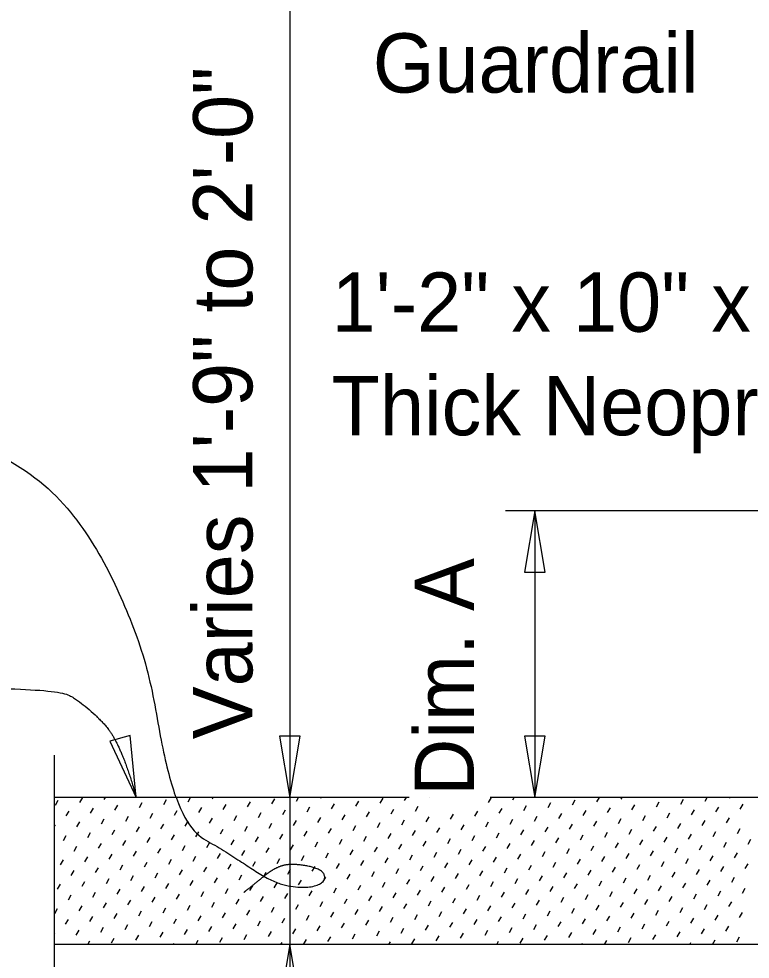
# Model space of a CAD drawing. Extents: x 21516.9 to 21589, y 56153.3 to 56193.5.
# Drawn here: x 21520.841 to 21523.329, y 56182.575 to 56185.773 of the extents above; entities that cross this region are included whole.
import ezdxf

# ---------------------------------------------------------------- set-up
doc = ezdxf.new("R2010")
doc.units = 0
for name, color, linetype in [('AdhocPoint_dp', 7, 'Continuous'), ('PlotBorder_dp', 7, 'Continuous'), ('SheetBorder_dp', 7, 'Continuous'), ('TextMisc', 7, 'Continuous')]:
    doc.layers.add(name, color=color, linetype=linetype)

msp = doc.modelspace()

# ---------------------------------------------------------------- linework, layer by layer
at = {"layer": 'AdhocPoint_dp'}
msp.add_line((21524.8963, 56182.6248), (21520.9629, 56182.6248), dxfattribs=at)
at = {"layer": 'PlotBorder_dp'}
for p, q in [((21521.7632, 56188.4582), (21521.7632, 56181.4582)), ((21524.9938, 56184.0995), (21522.4966, 56184.0995)), ((21522.5966, 56184.0995), (21522.5966, 56183.1248))]:
    msp.add_line(p, q, dxfattribs=at)
for points in [[(21522.5966, 56184.0995), (21522.5614, 56183.8912), (21522.6319, 56183.8912)], [(21521.2406, 56183.1248), (21521.2194, 56183.335), (21521.1513, 56183.3162)], [(21521.7632, 56183.1248), (21521.7985, 56183.3331), (21521.7279, 56183.3331)], [(21522.5966, 56183.1248), (21522.6319, 56183.3331), (21522.5614, 56183.3331)], [(21521.7632, 56182.6248), (21521.7279, 56182.4166), (21521.7985, 56182.4166)]]:
    msp.add_lwpolyline(points, close=True, dxfattribs=at)
msp.add_lwpolyline([(21520.963, 56181.2978), (21520.963, 56182.1975), (21520.8597, 56182.1975), (21520.963, 56182.2425), (21521.0664, 56182.2875), (21520.963, 56182.2875), (21520.963, 56183.2682)], dxfattribs=at)
for points in [[(21519.9826, 56184.4791), (21520.8234, 56184.3928), (21521.2569, 56183.7454), (21521.3674, 56183.0454), (21521.5657, 56182.9278), (21521.7074, 56182.8329), (21521.8124, 56182.8145), (21521.8818, 56182.833), (21521.8818, 56182.8741), (21521.8109, 56182.8968), (21521.7245, 56182.8968), (21521.6338, 56182.823), (21521.6069, 56182.8017)], [(21520.2586, 56183.4916), (21520.9544, 56183.5086), (21521.0791, 56183.432), (21521.1896, 56183.31), (21521.2406, 56183.1248)]]:
    msp.add_open_spline(points, degree=2, dxfattribs=at)
at = {"layer": 'TextMisc'}
for p, q in [((21522.1691, 56183.1248), (21520.9629, 56183.1248)), ((21520.9657, 56183.0984), (21520.9755, 56183.1152)), ((21521.0487, 56183.1081), (21521.0584, 56183.1248)), ((21521.1316, 56183.1178), (21521.1357, 56183.1248)), ((21521.3341, 56183.1007), (21521.3438, 56183.1175)), ((21521.417, 56183.1104), (21521.4254, 56183.1248)), ((21521.5, 56183.1201), (21521.5027, 56183.1248)), ((21521.6195, 56183.0932), (21521.6292, 56183.11)), ((21521.7024, 56183.1029), (21521.7122, 56183.1197)), ((21521.7854, 56183.1127), (21521.7924, 56183.1248)), ((21521.8683, 56183.1224), (21521.8697, 56183.1248)), ((21521.9879, 56183.0955), (21521.9976, 56183.1123)), ((21522.0708, 56183.1052), (21522.0805, 56183.122)), ((21522.1537, 56183.1149), (21522.1595, 56183.1248)), ((21522.2367, 56183.1247), (21522.2368, 56183.1248)), ((21522.4392, 56183.1075), (21522.4489, 56183.1243)), ((21524.955, 56183.1248), (21522.4449, 56183.1248)), ((21522.5221, 56183.1172), (21522.5265, 56183.1248)), ((21522.7246, 56183.1001), (21522.7343, 56183.1169)), ((21522.8075, 56183.1098), (21522.8162, 56183.1248)), ((21522.8905, 56183.1195), (21522.8935, 56183.1248)), ((21523.0929, 56183.1024), (21523.1027, 56183.1191)), ((21523.1759, 56183.1121), (21523.1833, 56183.1248)), ((21523.2588, 56183.1218), (21523.2606, 56183.1248)), ((21521.0023, 56183.0618), (21521.0121, 56183.0786)), ((21521.0853, 56183.0715), (21521.095, 56183.0883)), ((21521.1682, 56183.0812), (21521.1779, 56183.098)), ((21521.2512, 56183.0909), (21521.2609, 56183.1077)), ((21521.3707, 56183.0641), (21521.3804, 56183.0808)), ((21521.4536, 56183.0738), (21521.4634, 56183.0906)), ((21521.5366, 56183.0835), (21521.5463, 56183.1003)), ((21521.7391, 56183.0663), (21521.7488, 56183.0831)), ((21521.822, 56183.0761), (21521.8317, 56183.0929)), ((21521.9049, 56183.0858), (21521.9147, 56183.1026)), ((21522.1074, 56183.0686), (21522.1171, 56183.0854)), ((21522.1904, 56183.0783), (21522.2001, 56183.0951)), ((21522.3928, 56183.0612), (21522.4026, 56183.078)), ((21522.4758, 56183.0709), (21522.4855, 56183.0877)), ((21522.5587, 56183.0806), (21522.5684, 56183.0974)), ((21522.6416, 56183.0903), (21522.6514, 56183.1071)), ((21522.7612, 56183.0635), (21522.7709, 56183.0803)), ((21522.8441, 56183.0732), (21522.8539, 56183.09)), ((21522.9271, 56183.0829), (21522.9368, 56183.0997)), ((21523.01, 56183.0926), (21523.0197, 56183.1094)), ((21523.1296, 56183.0657), (21523.1393, 56183.0825)), ((21523.2125, 56183.0755), (21523.2222, 56183.0923)), ((21523.2954, 56183.0852), (21523.3052, 56183.102)), ((21521.1219, 56183.0349), (21521.1316, 56183.0517)), ((21521.2048, 56183.0446), (21521.2145, 56183.0614)), ((21521.2878, 56183.0543), (21521.2975, 56183.0711)), ((21521.4902, 56183.0372), (21521.5, 56183.054)), ((21521.5732, 56183.0469), (21521.5829, 56183.0637)), ((21521.6561, 56183.0566), (21521.6658, 56183.0734)), ((21521.7757, 56183.0297), (21521.7854, 56183.0465)), ((21521.8586, 56183.0395), (21521.8683, 56183.0562)), ((21521.9415, 56183.0492), (21521.9513, 56183.066)), ((21522.0245, 56183.0589), (21522.0342, 56183.0757)), ((21522.144, 56183.032), (21522.1537, 56183.0488)), ((21522.227, 56183.0417), (21522.2367, 56183.0585)), ((21522.3099, 56183.0515), (21522.3196, 56183.0683)), ((21522.5124, 56183.0343), (21522.5221, 56183.0511)), ((21522.5953, 56183.044), (21522.605, 56183.0608)), ((21522.6783, 56183.0537), (21522.688, 56183.0705)), ((21522.8807, 56183.0366), (21522.8905, 56183.0534)), ((21522.9637, 56183.0463), (21522.9734, 56183.0631)), ((21523.0466, 56183.056), (21523.0563, 56183.0728)), ((21523.1662, 56183.0291), (21523.1759, 56183.0459)), ((21523.2491, 56183.0389), (21523.2588, 56183.0557)), ((21520.9629, 56183.0274), (21520.9657, 56183.0322)), ((21521.0389, 56183.0252), (21521.0487, 56183.042)), ((21521.1585, 56182.9983), (21521.1682, 56183.0151)), ((21521.2414, 56183.008), (21521.2512, 56183.0248)), ((21521.3244, 56183.0177), (21521.3341, 56183.0345)), ((21521.4073, 56183.0274), (21521.417, 56183.0442)), ((21521.5269, 56183.0006), (21521.5366, 56183.0174)), ((21521.6098, 56183.0103), (21521.6195, 56183.0271)), ((21521.6927, 56183.02), (21521.7024, 56183.0368)), ((21521.8952, 56183.0028), (21521.9049, 56183.0196)), ((21521.9781, 56183.0126), (21521.9879, 56183.0294)), ((21522.0611, 56183.0223), (21522.0708, 56183.0391)), ((21522.2636, 56183.0051), (21522.2733, 56183.0219)), ((21522.3465, 56183.0148), (21522.3562, 56183.0316)), ((21522.4294, 56183.0246), (21522.4392, 56183.0414)), ((21522.549, 56182.9977), (21522.5587, 56183.0145)), ((21522.6319, 56183.0074), (21522.6416, 56183.0242)), ((21522.7149, 56183.0171), (21522.7246, 56183.0339)), ((21522.7978, 56183.0269), (21522.8075, 56183.0436)), ((21522.9173, 56183), (21522.9271, 56183.0168)), ((21523.0003, 56183.0097), (21523.01, 56183.0265)), ((21523.0832, 56183.0194), (21523.0929, 56183.0362)), ((21523.2857, 56183.0023), (21523.2954, 56183.019)), ((21520.9926, 56182.9788), (21521.0023, 56182.9956)), ((21521.0756, 56182.9886), (21521.0853, 56183.0053)), ((21521.278, 56182.9714), (21521.2878, 56182.9882)), ((21521.361, 56182.9811), (21521.3707, 56182.9979)), ((21521.4439, 56182.9908), (21521.4536, 56183.0076)), ((21521.6464, 56182.9737), (21521.6561, 56182.9905)), ((21521.7293, 56182.9834), (21521.7391, 56183.0002)), ((21521.8123, 56182.9931), (21521.822, 56183.0099)), ((21521.9318, 56182.9662), (21521.9415, 56182.983)), ((21522.0148, 56182.976), (21522.0245, 56182.9928)), ((21522.0977, 56182.9857), (21522.1074, 56183.0025)), ((21522.1806, 56182.9954), (21522.1904, 56183.0122)), ((21522.3002, 56182.9685), (21522.3099, 56182.9853)), ((21522.3831, 56182.9782), (21522.3928, 56182.995)), ((21522.4661, 56182.988), (21522.4758, 56183.0048)), ((21522.6685, 56182.9708), (21522.6783, 56182.9876)), ((21522.7515, 56182.9805), (21522.7612, 56182.9973)), ((21522.8344, 56182.9902), (21522.8441, 56183.007)), ((21523.0369, 56182.9731), (21523.0466, 56182.9899)), ((21523.1198, 56182.9828), (21523.1296, 56182.9996)), ((21523.2028, 56182.9925), (21523.2125, 56183.0093)), ((21523.3223, 56182.9656), (21523.332, 56182.9824)), ((21521.0292, 56182.9422), (21521.0389, 56182.959)), ((21521.1122, 56182.9519), (21521.1219, 56182.9687)), ((21521.1951, 56182.9617), (21521.2048, 56182.9785)), ((21521.3146, 56182.9348), (21521.3244, 56182.9516)), ((21521.3976, 56182.9445), (21521.4073, 56182.9613)), ((21521.4805, 56182.9542), (21521.4902, 56182.971)), ((21521.5635, 56182.964), (21521.5732, 56182.9807)), ((21521.683, 56182.9371), (21521.6927, 56182.9539)), ((21521.7659, 56182.9468), (21521.7757, 56182.9636)), ((21521.8489, 56182.9565), (21521.8586, 56182.9733)), ((21522.0514, 56182.9394), (21522.0611, 56182.9561)), ((21522.1343, 56182.9491), (21522.144, 56182.9659)), ((21522.2172, 56182.9588), (21522.227, 56182.9756)), ((21522.4197, 56182.9416), (21522.4294, 56182.9584)), ((21522.5027, 56182.9514), (21522.5124, 56182.9682)), ((21522.5856, 56182.9611), (21522.5953, 56182.9779)), ((21522.7051, 56182.9342), (21522.7149, 56182.951)), ((21522.7881, 56182.9439), (21522.7978, 56182.9607)), ((21522.871, 56182.9536), (21522.8807, 56182.9704)), ((21522.954, 56182.9634), (21522.9637, 56182.9802)), ((21523.0735, 56182.9365), (21523.0832, 56182.9533)), ((21523.1564, 56182.9462), (21523.1662, 56182.963)), ((21523.2394, 56182.9559), (21523.2491, 56182.9727)), ((21521.0658, 56182.9056), (21521.0756, 56182.9224)), ((21521.1488, 56182.9153), (21521.1585, 56182.9321)), ((21521.2317, 56182.9251), (21521.2414, 56182.9419)), ((21521.4342, 56182.9079), (21521.4439, 56182.9247)), ((21521.5171, 56182.9176), (21521.5269, 56182.9344)), ((21521.6001, 56182.9273), (21521.6098, 56182.9441)), ((21521.8025, 56182.9102), (21521.8123, 56182.927)), ((21521.8855, 56182.9199), (21521.8952, 56182.9367)), ((21521.9684, 56182.9296), (21521.9781, 56182.9464)), ((21522.088, 56182.9027), (21522.0977, 56182.9195)), ((21522.1709, 56182.9125), (21522.1806, 56182.9293)), ((21522.2538, 56182.9222), (21522.2636, 56182.939)), ((21522.3368, 56182.9319), (21522.3465, 56182.9487)), ((21522.4563, 56182.905), (21522.4661, 56182.9218)), ((21522.5393, 56182.9147), (21522.549, 56182.9315)), ((21522.6222, 56182.9245), (21522.6319, 56182.9413)), ((21522.8247, 56182.9073), (21522.8344, 56182.9241)), ((21522.9076, 56182.917), (21522.9173, 56182.9338)), ((21522.9906, 56182.9268), (21523.0003, 56182.9435)), ((21523.193, 56182.9096), (21523.2028, 56182.9264)), ((21523.276, 56182.9193), (21523.2857, 56182.9361)), ((21520.9829, 56182.8959), (21520.9926, 56182.9127)), ((21521.1024, 56182.869), (21521.1122, 56182.8858)), ((21521.1854, 56182.8787), (21521.1951, 56182.8955)), ((21521.2683, 56182.8885), (21521.278, 56182.9052)), ((21521.3513, 56182.8982), (21521.361, 56182.915)), ((21521.4708, 56182.8713), (21521.4805, 56182.8881)), ((21521.5537, 56182.881), (21521.5635, 56182.8978)), ((21521.6367, 56182.8907), (21521.6464, 56182.9075)), ((21521.7196, 56182.9005), (21521.7293, 56182.9173)), ((21521.8392, 56182.8736), (21521.8489, 56182.8904)), ((21521.9221, 56182.8833), (21521.9318, 56182.9001)), ((21522.005, 56182.893), (21522.0148, 56182.9098)), ((21522.2075, 56182.8759), (21522.2172, 56182.8927)), ((21522.2905, 56182.8856), (21522.3002, 56182.9024)), ((21522.3734, 56182.8953), (21522.3831, 56182.9121)), ((21522.5759, 56182.8781), (21522.5856, 56182.8949)), ((21522.6588, 56182.8879), (21522.6685, 56182.9047)), ((21522.7417, 56182.8976), (21522.7515, 56182.9144)), ((21522.8613, 56182.8707), (21522.871, 56182.8875)), ((21522.9442, 56182.8804), (21522.954, 56182.8972)), ((21523.0272, 56182.8901), (21523.0369, 56182.9069)), ((21523.1101, 56182.8999), (21523.1198, 56182.9167)), ((21523.2297, 56182.873), (21523.2394, 56182.8898)), ((21523.3126, 56182.8827), (21523.3223, 56182.8995)), ((21521.0195, 56182.8593), (21521.0292, 56182.8761)), ((21521.222, 56182.8421), (21521.2317, 56182.8589)), ((21521.3049, 56182.8518), (21521.3146, 56182.8686)), ((21521.3879, 56182.8616), (21521.3976, 56182.8784)), ((21521.5903, 56182.8444), (21521.6001, 56182.8612)), ((21521.6733, 56182.8541), (21521.683, 56182.8709)), ((21521.7562, 56182.8639), (21521.7659, 56182.8806)), ((21521.8758, 56182.837), (21521.8855, 56182.8538)), ((21521.9587, 56182.8467), (21521.9684, 56182.8635)), ((21522.0416, 56182.8564), (21522.0514, 56182.8732)), ((21522.1246, 56182.8661), (21522.1343, 56182.8829)), ((21522.2441, 56182.8393), (21522.2538, 56182.856)), ((21522.3271, 56182.849), (21522.3368, 56182.8658)), ((21522.41, 56182.8587), (21522.4197, 56182.8755)), ((21522.4929, 56182.8684), (21522.5027, 56182.8852)), ((21522.6125, 56182.8415), (21522.6222, 56182.8583)), ((21522.6954, 56182.8513), (21522.7051, 56182.8681)), ((21522.7784, 56182.861), (21522.7881, 56182.8778)), ((21522.9808, 56182.8438), (21522.9906, 56182.8606)), ((21523.0638, 56182.8535), (21523.0735, 56182.8703)), ((21523.1467, 56182.8633), (21523.1564, 56182.8801)), ((21520.9732, 56182.813), (21520.9829, 56182.8297)), ((21521.0561, 56182.8227), (21521.0658, 56182.8395)), ((21521.139, 56182.8324), (21521.1488, 56182.8492)), ((21521.2586, 56182.8055), (21521.2683, 56182.8223)), ((21521.3415, 56182.8152), (21521.3513, 56182.832)), ((21521.4245, 56182.825), (21521.4342, 56182.8418)), ((21521.5074, 56182.8347), (21521.5171, 56182.8515)), ((21521.627, 56182.8078), (21521.6367, 56182.8246)), ((21521.7099, 56182.8175), (21521.7196, 56182.8343)), ((21521.7928, 56182.8272), (21521.8025, 56182.844)), ((21521.9953, 56182.8101), (21522.005, 56182.8269)), ((21522.0782, 56182.8198), (21522.088, 56182.8366)), ((21522.1612, 56182.8295), (21522.1709, 56182.8463)), ((21522.3637, 56182.8124), (21522.3734, 56182.8292)), ((21522.4466, 56182.8221), (21522.4563, 56182.8389)), ((21522.5295, 56182.8318), (21522.5393, 56182.8486)), ((21522.6491, 56182.8049), (21522.6588, 56182.8217)), ((21522.732, 56182.8146), (21522.7417, 56182.8314)), ((21522.815, 56182.8244), (21522.8247, 56182.8412)), ((21522.8979, 56182.8341), (21522.9076, 56182.8509)), ((21523.0174, 56182.8072), (21523.0272, 56182.824)), ((21523.1004, 56182.8169), (21523.1101, 56182.8337)), ((21523.1833, 56182.8267), (21523.193, 56182.8434)), ((21523.2663, 56182.8364), (21523.276, 56182.8532)), ((21521.0098, 56182.7763), (21521.0195, 56182.7931)), ((21521.0927, 56182.7861), (21521.1024, 56182.8029)), ((21521.1757, 56182.7958), (21521.1854, 56182.8126)), ((21521.3781, 56182.7786), (21521.3879, 56182.7954)), ((21521.4611, 56182.7884), (21521.4708, 56182.8051)), ((21521.544, 56182.7981), (21521.5537, 56182.8149)), ((21521.7465, 56182.7809), (21521.7562, 56182.7977)), ((21521.8294, 56182.7906), (21521.8392, 56182.8074)), ((21521.9124, 56182.8004), (21521.9221, 56182.8172)), ((21522.0319, 56182.7735), (21522.0416, 56182.7903)), ((21522.1149, 56182.7832), (21522.1246, 56182.8)), ((21522.1978, 56182.7929), (21522.2075, 56182.8097)), ((21522.2807, 56182.8026), (21522.2905, 56182.8194)), ((21522.4003, 56182.7758), (21522.41, 56182.7926)), ((21522.4832, 56182.7855), (21522.4929, 56182.8023)), ((21522.5662, 56182.7952), (21522.5759, 56182.812)), ((21522.7686, 56182.778), (21522.7784, 56182.7948)), ((21522.8516, 56182.7878), (21522.8613, 56182.8046)), ((21522.9345, 56182.7975), (21522.9442, 56182.8143)), ((21523.137, 56182.7803), (21523.1467, 56182.7971)), ((21523.2199, 56182.79), (21523.2297, 56182.8068)), ((21523.3029, 56182.7998), (21523.3126, 56182.8166)), ((21521.1293, 56182.7495), (21521.139, 56182.7663)), ((21521.2123, 56182.7592), (21521.222, 56182.776)), ((21521.2952, 56182.7689), (21521.3049, 56182.7857)), ((21521.4147, 56182.742), (21521.4245, 56182.7588)), ((21521.4977, 56182.7517), (21521.5074, 56182.7685)), ((21521.5806, 56182.7615), (21521.5903, 56182.7783)), ((21521.6636, 56182.7712), (21521.6733, 56182.788)), ((21521.7831, 56182.7443), (21521.7928, 56182.7611)), ((21521.866, 56182.754), (21521.8758, 56182.7708)), ((21521.949, 56182.7638), (21521.9587, 56182.7805)), ((21522.1515, 56182.7466), (21522.1612, 56182.7634)), ((21522.2344, 56182.7563), (21522.2441, 56182.7731)), ((21522.3173, 56182.766), (21522.3271, 56182.7828)), ((21522.5198, 56182.7489), (21522.5295, 56182.7657)), ((21522.6028, 56182.7586), (21522.6125, 56182.7754)), ((21522.6857, 56182.7683), (21522.6954, 56182.7851)), ((21522.8052, 56182.7414), (21522.815, 56182.7582)), ((21522.8882, 56182.7512), (21522.8979, 56182.768)), ((21522.9711, 56182.7609), (21522.9808, 56182.7777)), ((21523.0541, 56182.7706), (21523.0638, 56182.7874)), ((21523.1736, 56182.7437), (21523.1833, 56182.7605)), ((21523.2565, 56182.7534), (21523.2663, 56182.7702)), ((21520.9634, 56182.73), (21520.9732, 56182.7468)), ((21521.0464, 56182.7397), (21521.0561, 56182.7565)), ((21521.1659, 56182.7129), (21521.1757, 56182.7296)), ((21521.2489, 56182.7226), (21521.2586, 56182.7394)), ((21521.3318, 56182.7323), (21521.3415, 56182.7491)), ((21521.5343, 56182.7151), (21521.544, 56182.7319)), ((21521.6172, 56182.7249), (21521.627, 56182.7417)), ((21521.7002, 56182.7346), (21521.7099, 56182.7514)), ((21521.9026, 56182.7174), (21521.9124, 56182.7342)), ((21521.9856, 56182.7271), (21521.9953, 56182.7439)), ((21522.0685, 56182.7369), (21522.0782, 56182.7537)), ((21522.1881, 56182.71), (21522.1978, 56182.7268)), ((21522.271, 56182.7197), (21522.2807, 56182.7365)), ((21522.3539, 56182.7294), (21522.3637, 56182.7462)), ((21522.4369, 56182.7392), (21522.4466, 56182.7559)), ((21522.5564, 56182.7123), (21522.5662, 56182.7291)), ((21522.6394, 56182.722), (21522.6491, 56182.7388)), ((21522.7223, 56182.7317), (21522.732, 56182.7485)), ((21522.9248, 56182.7145), (21522.9345, 56182.7313)), ((21523.0077, 56182.7243), (21523.0174, 56182.7411)), ((21523.0907, 56182.734), (21523.1004, 56182.7508)), ((21523.2931, 56182.7168), (21523.3029, 56182.7336)), ((21521.0001, 56182.6934), (21521.0098, 56182.7102)), ((21521.083, 56182.7031), (21521.0927, 56182.7199)), ((21521.2855, 56182.686), (21521.2952, 56182.7028)), ((21521.3684, 56182.6957), (21521.3781, 56182.7125)), ((21521.4514, 56182.7054), (21521.4611, 56182.7222)), ((21521.5709, 56182.6785), (21521.5806, 56182.6953)), ((21521.6538, 56182.6883), (21521.6636, 56182.705)), ((21521.7368, 56182.698), (21521.7465, 56182.7148)), ((21521.8197, 56182.7077), (21521.8294, 56182.7245)), ((21521.9393, 56182.6808), (21521.949, 56182.6976)), ((21522.0222, 56182.6905), (21522.0319, 56182.7073)), ((21522.1051, 56182.7003), (21522.1149, 56182.7171)), ((21522.3076, 56182.6831), (21522.3173, 56182.6999)), ((21522.3906, 56182.6928), (21522.4003, 56182.7096)), ((21522.4735, 56182.7025), (21522.4832, 56182.7193)), ((21522.676, 56182.6854), (21522.6857, 56182.7022)), ((21522.7589, 56182.6951), (21522.7686, 56182.7119)), ((21522.8418, 56182.7048), (21522.8516, 56182.7216)), ((21522.9614, 56182.6779), (21522.9711, 56182.6947)), ((21523.0443, 56182.6877), (21523.0541, 56182.7045)), ((21523.1273, 56182.6974), (21523.137, 56182.7142)), ((21523.2102, 56182.7071), (21523.2199, 56182.7239)), ((21520.9629, 56182.663), (21520.9634, 56182.6639)), ((21521.0367, 56182.6568), (21521.0464, 56182.6736)), ((21521.1196, 56182.6665), (21521.1293, 56182.6833)), ((21521.2025, 56182.6762), (21521.2123, 56182.693)), ((21521.3221, 56182.6494), (21521.3318, 56182.6662)), ((21521.405, 56182.6591), (21521.4147, 56182.6759)), ((21521.488, 56182.6688), (21521.4977, 56182.6856)), ((21521.6904, 56182.6516), (21521.7002, 56182.6684)), ((21521.7734, 56182.6614), (21521.7831, 56182.6782)), ((21521.8563, 56182.6711), (21521.866, 56182.6879)), ((21522.0588, 56182.6539), (21522.0685, 56182.6707)), ((21522.1417, 56182.6637), (21522.1515, 56182.6804)), ((21522.2247, 56182.6734), (21522.2344, 56182.6902)), ((21522.3442, 56182.6465), (21522.3539, 56182.6633)), ((21522.4272, 56182.6562), (21522.4369, 56182.673)), ((21522.5101, 56182.6659), (21522.5198, 56182.6827)), ((21522.593, 56182.6757), (21522.6028, 56182.6925)), ((21522.7126, 56182.6488), (21522.7223, 56182.6656)), ((21522.7955, 56182.6585), (21522.8052, 56182.6753)), ((21522.8785, 56182.6682), (21522.8882, 56182.685)), ((21523.0809, 56182.6511), (21523.0907, 56182.6679)), ((21523.1639, 56182.6608), (21523.1736, 56182.6776)), ((21523.2468, 56182.6705), (21523.2565, 56182.6873)), ((21521.076, 56182.6248), (21521.083, 56182.637)), ((21521.1562, 56182.6299), (21521.1659, 56182.6467)), ((21521.2391, 56182.6396), (21521.2489, 56182.6564)), ((21521.443, 56182.6248), (21521.4514, 56182.6393)), ((21521.5246, 56182.6322), (21521.5343, 56182.649)), ((21521.6075, 56182.6419), (21521.6172, 56182.6587)), ((21521.7327, 56182.6248), (21521.7368, 56182.6318)), ((21521.81, 56182.6248), (21521.8197, 56182.6416)), ((21521.8929, 56182.6345), (21521.9026, 56182.6513)), ((21521.9759, 56182.6442), (21521.9856, 56182.661)), ((21522.0998, 56182.6248), (21522.1051, 56182.6341)), ((21522.1783, 56182.627), (21522.1881, 56182.6438)), ((21522.2613, 56182.6368), (21522.271, 56182.6536)), ((21522.4668, 56182.6248), (21522.4735, 56182.6364)), ((21522.5467, 56182.6293), (21522.5564, 56182.6461)), ((21522.6296, 56182.6391), (21522.6394, 56182.6558)), ((21522.8338, 56182.6248), (21522.8418, 56182.6387)), ((21522.9151, 56182.6316), (21522.9248, 56182.6484)), ((21522.998, 56182.6413), (21523.0077, 56182.6581)), ((21523.1236, 56182.6248), (21523.1273, 56182.6312)), ((21523.2009, 56182.6248), (21523.2102, 56182.641)), ((21523.2834, 56182.6339), (21523.2931, 56182.6507)), ((21520.9986, 56182.6248), (21521.0001, 56182.6273)), ((21521.3657, 56182.6248), (21521.3684, 56182.6295)), ((21522.3895, 56182.6248), (21522.3906, 56182.6267)), ((21522.7565, 56182.6248), (21522.7589, 56182.629))]:
    msp.add_line(p, q, dxfattribs=at)

# ---------------------------------------------------------------- texts
at = {"layer": 'PlotBorder_dp'}
for s, p in [('Guardrail', (21522.0454, 56185.522)), ('1\'-2" x 10" x ', (21521.9051, 56184.7086)), ('Thick Neoprene Pad', (21521.9051, 56184.3565))]:
    msp.add_text(s, height=0.2016, dxfattribs=at).set_placement(p)
at = {"layer": 'SheetBorder_dp'}
for s, p in [('Varies 1\'-9" to 2\'-0"', (21521.6358, 56183.3227)), ('Dim. A', (21522.3893, 56183.1301))]:
    msp.add_text(s, height=0.2016, rotation=90, dxfattribs=at).set_placement(p)

doc.saveas('drawing.dxf')
